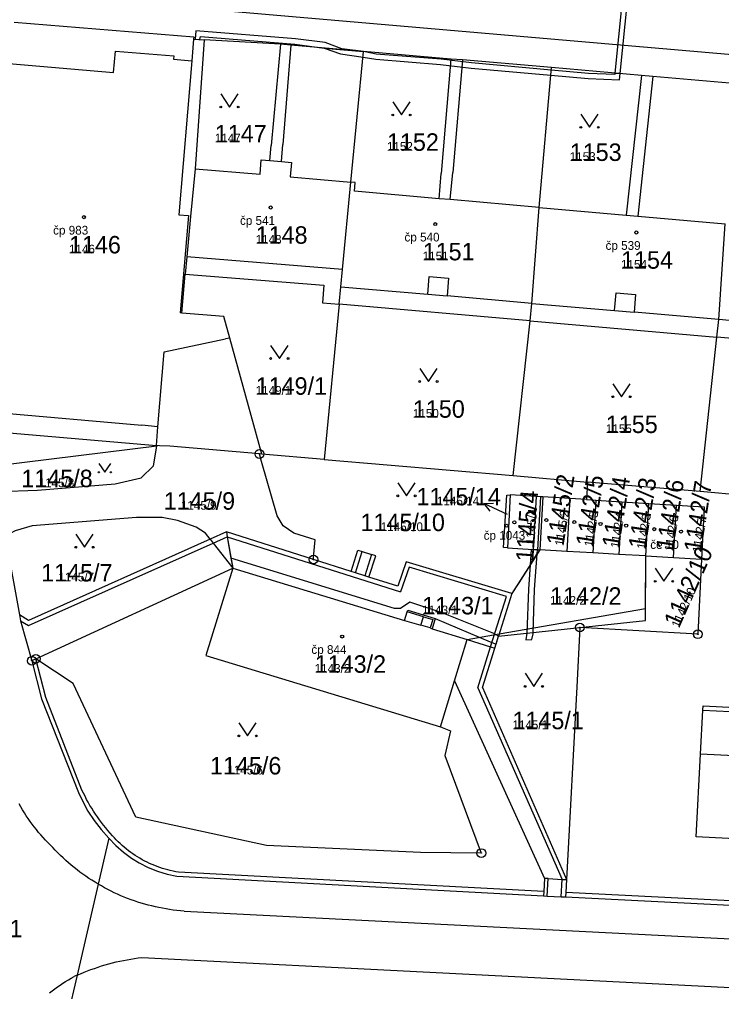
# Model space of a CAD drawing. Extents: x -763628 to -761565, y -976033 to -973833.
# Drawn here: x -762312.8 to -762232.3, y -975218.9 to -975107.6 of the extents above; entities that cross this region are included whole.
import ezdxf

# ---------------------------------------------------------------- set-up
doc = ezdxf.new("R2010")
doc.units = 0
for name, color, linetype in [('KN_cisla parcel 1000', 7, 'Continuous'), ('KN_cisla parcel 500', 7, 'Continuous'), ('KN_cisla parcel znacky', 7, 'Continuous'), ('KN_cisla popisna 500', 7, 'Continuous'), ('KN_hranice parcel', 7, 'Continuous'), ('KN_vecna bremena', 7, 'Continuous'), ('KN_vnitrni kresba parcel', 7, 'Continuous'), ('KN_znacky bodu BP', 7, 'Continuous'), ('KN_znacky budov', 7, 'Continuous'), ('KN_znacky kultur', 7, 'Continuous')]:
    doc.layers.add(name, color=color, linetype=linetype)

msp = doc.modelspace()

# ---------------------------------------------------------------- linework, layer by layer
at = {"layer": 'KN_cisla parcel znacky'}
for p, q in [((-762259.59, -975163.01), (-762258.47, -975162.98)), ((-762256.87, -975164.28), (-762259.59, -975163.01)), ((-762259.59, -975163.01), (-762258.89, -975163.89))]:
    msp.add_line(p, q, dxfattribs=at)
at = {"layer": 'KN_hranice parcel'}
for p, q in [((-762291.6, -975109.95), (-762292.65, -975124.69)), ((-762274.79, -975126.23), (-762273.34, -975111.26)), ((-762253.23, -975129.13), (-762251.83, -975113.12)), ((-762276.14, -975140.2), (-762277.84, -975157.98)), ((-762254.28, -975142.1), (-762276.14, -975140.2)), ((-762256.2, -975159.83), (-762254.28, -975142.1)), ((-762254.28, -975142.1), (-762232.88, -975143.96)), ((-762285.01, -975157.37), (-762288.68, -975144.08)), ((-762234.81, -975161.66), (-762232.88, -975143.96)), ((-762211.9, -975145.78), (-762232.88, -975143.96)), ((-762297.04, -975156.46), (-762315.51, -975158.72)), ((-762285.01, -975157.37), (-762285.28, -975157.35)), ((-762277.84, -975157.98), (-762285.01, -975157.37)), ((-762277.84, -975157.98), (-762256.2, -975159.83)), ((-762256.2, -975159.83), (-762247.7, -975160.56)), ((-762247.7, -975160.56), (-762247.81, -975162.58)), ((-762234.81, -975161.66), (-762247.7, -975160.56)), ((-762256.54, -975162.04), (-762256.88, -975168.08)), ((-762213.62, -975163.47), (-762234.81, -975161.66)), ((-762253.08, -975162.25), (-762253.42, -975168.33)), ((-762249.72, -975162.46), (-762250.05, -975168.51)), ((-762247.81, -975162.58), (-762249.72, -975162.46)), ((-762247.81, -975162.58), (-762246.75, -975162.65)), ((-762246.75, -975162.65), (-762247.08, -975168.68)), ((-762246.75, -975162.65), (-762243.78, -975162.83)), ((-762243.78, -975162.83), (-762244.11, -975168.84)), ((-762243.78, -975162.83), (-762240.67, -975163.02)), ((-762241, -975169.01), (-762240.67, -975163.02)), ((-762240.67, -975163.02), (-762237.5, -975163.22)), ((-762237.83, -975169.2), (-762237.5, -975163.22)), ((-762289.04, -975166.27), (-762290.9, -975167.1)), ((-762279.08, -975169.43), (-762289.04, -975166.27)), ((-762314.41, -975166.77), (-762312.74, -975175.77)), ((-762253.17, -975168.34), (-762256.35, -975173.33)), ((-762253.42, -975168.33), (-762253.17, -975168.34)), ((-762250.05, -975168.51), (-762253.17, -975168.34)), ((-762247.08, -975168.68), (-762250.05, -975168.51)), ((-762244.11, -975168.84), (-762247.08, -975168.68)), ((-762241, -975169.01), (-762244.11, -975168.84)), ((-762241, -975169.01), (-762237.83, -975169.2)), ((-762237.83, -975169.2), (-762234.66, -975169.38)), ((-762256.35, -975173.33), (-762257.89, -975178.21)), ((-762257.89, -975178.21), (-762248.58, -975177.21))]:
    msp.add_line(p, q, dxfattribs=at)
for points in [[(-762313.36, -975107.92), (-762292.79, -975109.61), (-762292.81, -975109.84), (-762291.6, -975109.95)], [(-762273.34, -975111.26), (-762281.67, -975110.54), (-762282.86, -975110.44), (-762291.6, -975109.95)], [(-762251.83, -975113.12), (-762262.01, -975112.24), (-762263.35, -975112.13), (-762273.34, -975111.26)], [(-762230.54, -975114.96), (-762240.22, -975114.12), (-762241.5, -975114.01), (-762251.83, -975113.12)], [(-762292.65, -975124.69), (-762285.2, -975125.33), (-762285.06, -975123.67), (-762284.1, -975123.75), (-762282.75, -975123.86), (-762281.6, -975123.96), (-762281.75, -975125.63), (-762274.79, -975126.23)], [(-762292.65, -975124.69), (-762293.16, -975130.17), (-762293.58, -975134.78), (-762293.76, -975136.76)], [(-762276.14, -975140.2), (-762275.95, -975138.21), (-762275.75, -975136.22), (-762274.79, -975126.23)], [(-762253.23, -975129.13), (-762263.41, -975128.23), (-762264.69, -975128.12), (-762274.39, -975127.27), (-762274.32, -975126.27), (-762274.79, -975126.23)], [(-762254.28, -975142.1), (-762254.07, -975140.11), (-762253.23, -975129.13)], [(-762253.23, -975129.13), (-762243.27, -975130), (-762241.95, -975130.12), (-762231.93, -975131)], [(-762232.88, -975143.96), (-762232.66, -975141.96), (-762231.93, -975131)], [(-762288.68, -975144.08), (-762289.36, -975141.6), (-762294.17, -975141.24), (-762293.76, -975136.76)], [(-762293.76, -975136.76), (-762277.9, -975138.04), (-762278.06, -975140.03), (-762276.14, -975140.2)], [(-762315.13, -975161.65), (-762310.69, -975161.48), (-762301.81, -975160.78), (-762298.83, -975160.07), (-762297.41, -975158.7), (-762297.04, -975156.46)], [(-762285.28, -975157.35), (-762295.55, -975156.47), (-762296.73, -975156.4), (-762297.06, -975156.37), (-762297.04, -975156.46)], [(-762279.08, -975169.43), (-762279.09, -975169.21), (-762278.88, -975167.18), (-762281.34, -975166.4), (-762282.55, -975165.59), (-762283.24, -975164.44), (-762285.02, -975158.21), (-762285.28, -975157.35)], [(-762256.88, -975168.08), (-762257.33, -975168.06), (-762256.92, -975162.05), (-762256.54, -975162.04)], [(-762253.08, -975162.25), (-762253.57, -975162.22), (-762256.54, -975162.04)], [(-762249.72, -975162.46), (-762252.83, -975162.27), (-762253.08, -975162.25)], [(-762237.5, -975163.22), (-762234.34, -975163.41), (-762234.66, -975169.38)], [(-762290.9, -975167.1), (-762291.44, -975166.4), (-762292.51, -975165.73), (-762294.67, -975164.95), (-762296.4, -975164.61), (-762299.35, -975164.63), (-762311.3, -975165.58), (-762313.26, -975166.16), (-762314.41, -975166.77)], [(-762289.04, -975166.27), (-762288.95, -975166.83), (-762288.33, -975170.44)], [(-762290.9, -975167.1), (-762311.71, -975176.42), (-762312.74, -975175.77)], [(-762256.88, -975168.08), (-762253.92, -975168.29), (-762253.42, -975168.33)], [(-762256.35, -975173.33), (-762268.48, -975169.68), (-762269.41, -975172.49), (-762272.73, -975171.44), (-762273.21, -975171.29), (-762274.28, -975170.95), (-762274.76, -975170.8), (-762279.08, -975169.43)], [(-762248.58, -975177.21), (-762241.05, -975176.43), (-762241, -975169.01)], [(-762234.66, -975169.38), (-762235.06, -975177.99), (-762248.58, -975177.21)], [(-762288.33, -975170.44), (-762291.41, -975180.43), (-762264.53, -975188.6)], [(-762288.33, -975170.44), (-762268.65, -975176.42), (-762268.34, -975175.41), (-762268.28, -975175.23), (-762265.14, -975176.18), (-762265.5, -975177.38), (-762261.49, -975178.6)], [(-762312.74, -975175.77), (-762312.62, -975176.44), (-762311.34, -975181.02)], [(-762248.58, -975177.21), (-762248.93, -975184), (-762250.1, -975206.07), (-762250.18, -975207.57), (-762250.2, -975208.06)], [(-762264.53, -975188.6), (-762262.92, -975183.31), (-762261.49, -975178.6)], [(-762261.49, -975178.6), (-762258.79, -975179.43), (-762258.32, -975179.57), (-762257.89, -975178.21)], [(-762264.53, -975188.6), (-762263.4, -975189.04), (-762264.05, -975191.88), (-762259.86, -975203.04), (-762266.82, -975202.96), (-762284.45, -975202.16), (-762299.41, -975198.93), (-762306.6, -975183.62), (-762310.88, -975180.81), (-762311.34, -975181.02)], [(-762311.34, -975181.02), (-762310.22, -975185.39), (-762306.01, -975196.11)], [(-762234.76, -975191.72), (-762234.5, -975186.69), (-762234.47, -975186.19), (-762219.72, -975186.93)], [(-762219.92, -975191.02), (-762223.83, -975190.82), (-762223.9, -975192.26), (-762234.76, -975191.72)], [(-762190.63, -975193.94), (-762191.1, -975203.43), (-762205.94, -975202.68), (-762220.45, -975201.95), (-762235.26, -975201.2), (-762234.76, -975191.72)], [(-762306.01, -975196.11), (-762305.44, -975197.3), (-762304.92, -975198.23), (-762304.2, -975199.32), (-762303.39, -975200.36), (-762302.51, -975201.34)], [(-762302.51, -975201.34), (-762303.73, -975206.6), (-762306.15, -975217.03), (-762308.35, -975226.49)], [(-762302.51, -975201.34), (-762301.72, -975202.17), (-762300.85, -975202.94), (-762299.93, -975203.62), (-762299.04, -975204.17), (-762298.02, -975204.69), (-762296.95, -975205.12), (-762295.85, -975205.46), (-762294.72, -975205.7)], [(-762294.72, -975205.7), (-762252.72, -975207.94), (-762252.32, -975207.96), (-762250.7, -975208.05), (-762250.2, -975208.06)], [(-762250.2, -975208.06), (-762178.53, -975211.68), (-762178.13, -975211.7), (-762176.93, -975211.76), (-762176.53, -975211.78)]]:
    msp.add_lwpolyline(points, dxfattribs=at)
at = {"layer": 'KN_vecna bremena'}
msp.add_lwpolyline([(-762243.72, -975105.45), (-762244.55, -975113.75), (-762243.96, -975113.8), (-762243.12, -975105.51)], dxfattribs=at)
for points in [[(-762292.55, -975108.91), (-762292.63, -975109.86), (-762292.08, -975109.91), (-762292.01, -975109.55), (-762281.21, -975110.43), (-762277.87, -975110.87), (-762273.34, -975111.26), (-762275.83, -975110.95), (-762277.73, -975110.25), (-762281.13, -975109.83)], [(-762273.34, -975111.26), (-762277.87, -975110.87), (-762275.99, -975111.53), (-762273.41, -975111.93), (-762271.96, -975112.16), (-762264.52, -975112.76), (-762261.04, -975113.16), (-762251.91, -975113.98), (-762247.64, -975114.37), (-762244.03, -975114.53), (-762243.96, -975113.8), (-762244.55, -975113.75), (-762244.57, -975113.91), (-762247.6, -975113.77), (-762251.85, -975113.39), (-762261, -975112.56), (-762264.46, -975112.16), (-762271.9, -975111.56)], [(-762289.04, -975166.27), (-762288.95, -975166.83), (-762288.53, -975169.28), (-762288.33, -975170.44), (-762268.65, -975176.42), (-762268.34, -975175.41), (-762268.28, -975175.23), (-762265.14, -975176.18), (-762265.5, -975177.38), (-762261.49, -975178.6), (-762257.81, -975177.96), (-762241.04, -975175.05), (-762241, -975169.01), (-762244.11, -975168.84), (-762247.08, -975168.68), (-762250.05, -975168.51), (-762253.17, -975168.34), (-762255.57, -975172.11), (-762256.35, -975173.33), (-762268.48, -975169.68), (-762269.41, -975172.49), (-762272.73, -975171.44), (-762273.21, -975171.29), (-762274.28, -975170.95), (-762274.76, -975170.8), (-762279.08, -975169.43)], [(-762253.45, -975168.79), (-762254.27, -975170.06), (-762254.46, -975172.81), (-762254.63, -975177.86), (-762254.78, -975178.64), (-762254.06, -975178.59), (-762253.93, -975177.93), (-762253.93, -975177.78), (-762253.76, -975172.85)], [(-762254.27, -975170.06), (-762253.45, -975168.79), (-762253.42, -975168.33), (-762254.14, -975168.27)], [(-762269.12, -975175.06), (-762269.81, -975175.04), (-762288.53, -975169.28), (-762288.33, -975170.44), (-762268.65, -975176.42), (-762268.34, -975175.41), (-762268.28, -975175.23), (-762265.14, -975176.18), (-762258.84, -975178.84), (-762258.17, -975179.11), (-762257.89, -975178.21), (-762258.44, -975177.92), (-762264.36, -975175.53), (-762268.06, -975174.32)]]:
    msp.add_lwpolyline(points, close=True, dxfattribs=at)
at = {"layer": 'KN_vnitrni kresba parcel'}
for p, q in [((-762313.23, -975104.5), (-762213.18, -975113.18)), ((-762292.81, -975109.84), (-762293.02, -975112.33)), ((-762282.86, -975110.44), (-762283.94, -975122.03)), ((-762281.67, -975110.54), (-762282.59, -975121.93)), ((-762301.97, -975113.66), (-762301.77, -975111.22)), ((-762301.77, -975111.22), (-762295.07, -975111.78)), ((-762295.07, -975111.78), (-762295.1, -975112.15)), ((-762263.35, -975112.13), (-762264.45, -975125.22)), ((-762313.98, -975112.63), (-762301.97, -975113.66)), ((-762295.1, -975112.15), (-762293.02, -975112.33)), ((-762293.02, -975112.33), (-762294.5, -975129.97)), ((-762262.01, -975112.24), (-762263.14, -975125.13)), ((-762241.5, -975114.01), (-762243.27, -975130)), ((-762240.22, -975114.12), (-762241.95, -975130.12)), ((-762284.1, -975123.75), (-762283.94, -975122.03)), ((-762282.75, -975123.86), (-762282.59, -975121.93)), ((-762264.69, -975128.12), (-762264.45, -975125.22)), ((-762263.41, -975128.23), (-762263.14, -975125.13)), ((-762294.5, -975129.97), (-762293.4, -975130.06)), ((-762293.4, -975130.06), (-762294.34, -975141.18)), ((-762275.75, -975136.22), (-762293.58, -975134.78)), ((-762266, -975139.07), (-762265.83, -975137.03)), ((-762265.83, -975137.03), (-762263.61, -975137.23)), ((-762263.61, -975137.23), (-762263.79, -975139.26)), ((-762275.95, -975138.21), (-762266, -975139.07)), ((-762266, -975139.07), (-762263.79, -975139.26)), ((-762254.07, -975140.11), (-762263.79, -975139.26)), ((-762244.61, -975140.93), (-762244.43, -975138.89)), ((-762244.43, -975138.89), (-762242.19, -975139.08)), ((-762242.19, -975139.08), (-762242.37, -975141.12)), ((-762254.07, -975140.11), (-762244.61, -975140.93)), ((-762244.61, -975140.93), (-762242.37, -975141.12)), ((-762294.17, -975141.24), (-762294.34, -975141.18)), ((-762232.66, -975141.96), (-762242.37, -975141.12)), ((-762223.18, -975142.78), (-762232.66, -975141.96)), ((-762296.19, -975145.64), (-762289.16, -975144.18)), ((-762288.68, -975144.08), (-762289.16, -975144.18)), ((-762296.89, -975154.23), (-762296.19, -975145.64)), ((-762316.65, -975152.49), (-762298.74, -975154.07)), ((-762296.89, -975154.23), (-762298.74, -975154.07)), ((-762297.06, -975156.37), (-762296.89, -975154.23)), ((-762316.03, -975154.76), (-762297.06, -975156.37)), ((-762253.57, -975162.22), (-762253.92, -975168.29)), ((-762252.83, -975162.27), (-762253.17, -975168.34)), ((-762311.72, -975177), (-762290.56, -975167.55)), ((-762290.9, -975167.1), (-762290.56, -975167.55)), ((-762290.56, -975167.55), (-762288.95, -975166.83)), ((-762290.56, -975167.55), (-762288.33, -975170.44)), ((-762288.95, -975166.83), (-762269.1, -975173.12)), ((-762274.76, -975170.8), (-762273.99, -975168.37)), ((-762274.28, -975170.95), (-762273.5, -975168.53)), ((-762273.99, -975168.37), (-762273.5, -975168.53)), ((-762273.5, -975168.53), (-762272.44, -975168.86)), ((-762272.44, -975168.86), (-762273.21, -975171.29)), ((-762271.96, -975169.01), (-762272.44, -975168.86)), ((-762272.73, -975171.44), (-762271.96, -975169.01)), ((-762310.88, -975180.81), (-762288.33, -975170.44)), ((-762268.14, -975170.3), (-762269.1, -975173.12)), ((-762256.97, -975173.67), (-762268.14, -975170.3)), ((-762258.79, -975179.43), (-762256.97, -975173.67)), ((-762266.48, -975175.98), (-762268.34, -975175.41)), ((-762312.62, -975176.44), (-762311.72, -975177)), ((-762268.65, -975176.42), (-762266.78, -975176.94)), ((-762266.78, -975176.94), (-762266.48, -975175.98)), ((-762266.48, -975175.98), (-762265.43, -975176.3)), ((-762265.43, -975176.3), (-762265.72, -975177.26)), ((-762265.72, -975177.26), (-762266.78, -975176.94)), ((-762265.72, -975177.26), (-762265.5, -975177.38)), ((-762260.27, -975184.11), (-762258.79, -975179.43)), ((-762259.73, -975184.07), (-762258.32, -975179.57)), ((-762309.75, -975185.22), (-762310.88, -975180.81)), ((-762262.92, -975183.31), (-762252.61, -975205.94)), ((-762260.27, -975184.11), (-762250.6, -975206.05)), ((-762259.73, -975184.07), (-762250.1, -975206.07)), ((-762305.6, -975195.83), (-762309.75, -975185.22)), ((-762234.5, -975186.69), (-762219.74, -975187.43)), ((-762252.69, -975207.44), (-762294.55, -975205.23)), ((-762252.61, -975205.94), (-762252.69, -975207.44)), ((-762252.21, -975205.96), (-762252.61, -975205.94)), ((-762252.32, -975207.96), (-762252.21, -975205.96)), ((-762252.21, -975205.96), (-762250.6, -975206.05)), ((-762250.7, -975208.05), (-762250.6, -975206.05)), ((-762250.6, -975206.05), (-762250.1, -975206.07)), ((-762252.69, -975207.44), (-762252.72, -975207.94)), ((-762178.5, -975211.18), (-762250.18, -975207.57)), ((-762293.91, -975209.68), (-762200.41, -975214.45)), ((-762298.75, -975214.99), (-762200.57, -975220.01))]:
    msp.add_line(p, q, dxfattribs=at)
for points in [[(-762302.1, -975201.05), (-762302.36, -975200.76), (-762302.62, -975200.46), (-762302.88, -975200.16), (-762303.13, -975199.85), (-762303.37, -975199.54), (-762303.6, -975199.22), (-762303.83, -975198.9), (-762304.06, -975198.58), (-762304.27, -975198.25), (-762304.48, -975197.91), (-762304.69, -975197.58), (-762304.88, -975197.23), (-762305.07, -975196.89), (-762305.25, -975196.54), (-762305.43, -975196.19), (-762305.6, -975195.83)], [(-762308.94, -975202.41), (-762309.22, -975202.13), (-762309.5, -975201.85), (-762309.78, -975201.56), (-762310.04, -975201.27), (-762310.3, -975200.97), (-762310.56, -975200.67), (-762310.81, -975200.36), (-762311.06, -975200.05), (-762311.3, -975199.74), (-762311.53, -975199.42), (-762311.76, -975199.09), (-762311.98, -975198.76), (-762312.19, -975198.43), (-762312.4, -975198.09), (-762312.6, -975197.75), (-762312.8, -975197.4)], [(-762294.55, -975205.23), (-762294.86, -975205.18), (-762295.17, -975205.11), (-762295.48, -975205.05), (-762295.78, -975204.97), (-762296.08, -975204.89), (-762296.38, -975204.79), (-762296.68, -975204.7), (-762296.98, -975204.59), (-762297.27, -975204.48), (-762297.56, -975204.35), (-762297.85, -975204.23), (-762298.13, -975204.09), (-762298.41, -975203.95), (-762298.69, -975203.8), (-762298.96, -975203.64), (-762299.23, -975203.48), (-762299.5, -975203.31), (-762299.76, -975203.14), (-762300.02, -975202.96), (-762300.27, -975202.77), (-762300.52, -975202.57), (-762300.76, -975202.37), (-762300.99, -975202.17), (-762301.23, -975201.95), (-762301.45, -975201.74), (-762301.67, -975201.51), (-762301.89, -975201.28), (-762302.1, -975201.05)], [(-762303.73, -975206.6), (-762304.09, -975206.39), (-762304.45, -975206.16), (-762304.8, -975205.94), (-762305.15, -975205.7), (-762305.49, -975205.46), (-762305.83, -975205.21), (-762306.16, -975204.96), (-762306.49, -975204.7), (-762306.82, -975204.43), (-762307.14, -975204.16), (-762307.45, -975203.88), (-762307.76, -975203.6), (-762308.06, -975203.31), (-762308.36, -975203.02), (-762308.65, -975202.72), (-762308.94, -975202.41)], [(-762293.91, -975209.68), (-762294.32, -975209.65), (-762294.74, -975209.61), (-762295.15, -975209.56), (-762295.56, -975209.5), (-762295.97, -975209.43), (-762296.38, -975209.36), (-762296.79, -975209.28), (-762297.19, -975209.2), (-762297.6, -975209.1), (-762298, -975209), (-762298.4, -975208.89), (-762298.8, -975208.77), (-762299.2, -975208.65), (-762299.59, -975208.52), (-762299.98, -975208.38), (-762300.37, -975208.23), (-762300.76, -975208.08), (-762301.14, -975207.92), (-762301.52, -975207.75), (-762301.9, -975207.58), (-762302.27, -975207.39), (-762302.64, -975207.21), (-762303.01, -975207.01), (-762303.37, -975206.81), (-762303.73, -975206.6)], [(-762306.15, -975217.03), (-762305.76, -975216.86), (-762305.36, -975216.69), (-762304.97, -975216.54), (-762304.57, -975216.38), (-762304.16, -975216.24), (-762303.76, -975216.1), (-762303.35, -975215.97), (-762302.94, -975215.85), (-762302.53, -975215.73), (-762302.11, -975215.62), (-762301.7, -975215.51), (-762301.28, -975215.42), (-762300.86, -975215.33), (-762300.44, -975215.25), (-762300.02, -975215.17), (-762299.6, -975215.1), (-762299.18, -975215.04), (-762298.75, -975214.99)], [(-762309.3, -975219.04), (-762309.01, -975218.81), (-762308.71, -975218.59), (-762308.41, -975218.37), (-762308.1, -975218.15), (-762307.79, -975217.95), (-762307.47, -975217.75), (-762307.15, -975217.56), (-762306.83, -975217.37), (-762306.5, -975217.19)], [(-762306.15, -975217.03), (-762306.33, -975217.11), (-762306.5, -975217.19)]]:
    msp.add_lwpolyline(points, dxfattribs=at)
at = {"layer": 'KN_znacky bodu BP'}
for centre, radius in [((-762285.28, -975157.35), 0.5), ((-762285.28, -975157.35), 0.0303), ((-762279.08, -975169.43), 0.5), ((-762279.08, -975169.43), 0.0303), ((-762248.58, -975177.21), 0.5), ((-762248.58, -975177.21), 0.0303), ((-762235.06, -975177.99), 0.5), ((-762235.06, -975177.99), 0.0303), ((-762311.34, -975181.02), 0.5), ((-762310.88, -975180.81), 0.5), ((-762311.34, -975181.02), 0.0303), ((-762310.88, -975180.81), 0.0303), ((-762259.86, -975203.04), 0.5), ((-762259.86, -975203.04), 0.0303)]:
    msp.add_circle(centre, radius, dxfattribs=at)
at = {"layer": 'KN_znacky budov'}
for centre in [(-762283.98, -975129.13), (-762305.38, -975130.24), (-762265.14, -975131.03), (-762242.11, -975131.99), (-762256.95, -975165.57), (-762256.07, -975165.18), (-762252.41, -975164.92), (-762249.21, -975165.15), (-762246.21, -975165.36), (-762243.27, -975165.55), (-762240.06, -975165.96), (-762236.99, -975166.23), (-762275.8, -975178.25)]:
    msp.add_circle(centre, 0.175, dxfattribs=at)
at = {"layer": 'KN_znacky kultur'}
for points in [[(-762289.7, -975116.13), (-762288.7, -975117.63), (-762287.7, -975116.13)], [(-762270, -975117.04), (-762269, -975118.54), (-762268, -975117.04)], [(-762248.46, -975118.45), (-762247.46, -975119.95), (-762246.46, -975118.45)], [(-762283.99, -975144.92), (-762282.99, -975146.42), (-762281.99, -975144.92)], [(-762266.92, -975147.55), (-762265.92, -975149.05), (-762264.92, -975147.55)], [(-762244.8, -975149.3), (-762243.8, -975150.8), (-762242.8, -975149.3)], [(-762303.66, -975158.43), (-762302.98, -975159.45), (-762302.3, -975158.43)], [(-762269.43, -975160.64), (-762268.43, -975162.14), (-762267.43, -975160.64)], [(-762306.31, -975166.53), (-762305.31, -975168.03), (-762304.31, -975166.53)], [(-762239.94, -975170.43), (-762238.94, -975171.93), (-762237.94, -975170.43)], [(-762254.85, -975182.46), (-762253.85, -975183.96), (-762252.85, -975182.46)], [(-762287.63, -975188.13), (-762286.63, -975189.63), (-762285.63, -975188.13)]]:
    msp.add_lwpolyline(points, dxfattribs=at)
for centre, radius in [((-762289.7, -975117.63), 0.1), ((-762287.7, -975117.63), 0.1), ((-762270, -975118.54), 0.1), ((-762268, -975118.54), 0.1), ((-762248.46, -975119.95), 0.1), ((-762246.46, -975119.95), 0.1), ((-762283.99, -975146.42), 0.1), ((-762281.99, -975146.42), 0.1), ((-762266.92, -975149.05), 0.1), ((-762264.92, -975149.05), 0.1), ((-762244.8, -975150.8), 0.1), ((-762242.8, -975150.8), 0.1), ((-762303.66, -975159.45), 0.068), ((-762302.3, -975159.45), 0.068), ((-762269.43, -975162.14), 0.1), ((-762267.43, -975162.14), 0.1), ((-762306.31, -975168.03), 0.1), ((-762304.31, -975168.03), 0.1), ((-762239.94, -975171.93), 0.1), ((-762237.94, -975171.93), 0.1), ((-762254.85, -975183.96), 0.1), ((-762252.85, -975183.96), 0.1), ((-762287.63, -975189.63), 0.1), ((-762285.63, -975189.63), 0.1)]:
    msp.add_circle(centre, radius, dxfattribs=at)

# ---------------------------------------------------------------- texts
at = {"layer": 'KN_cisla parcel 1000'}
for s, p in [('1147', (-762290.39, -975121.68)), ('1152', (-762270.67, -975122.64)), ('1153', (-762249.74, -975123.8)), ('1148', (-762285.71, -975133.28)), ('1146', (-762307.09, -975134.39)), ('1151', (-762266.58, -975135.18)), ('1154', (-762243.86, -975136.14)), ('1149/1', (-762285.71, -975150.57)), ('1150', (-762267.7, -975153.2)), ('1155', (-762245.6, -975154.95)), ('1145/8', (-762312.55, -975161.15)), ('1145/9', (-762296.24, -975163.73)), ('1145/14', (-762267.29, -975163.23)), ('1145/10', (-762273.7, -975166.18)), ('1145/7', (-762310.28, -975171.94)), ('1142/2', (-762251.99, -975174.61)), ('1143/1', (-762266.64, -975175.71)), ('1143/2', (-762278.95, -975182.4)), ('1145/1', (-762256.3, -975188.86)), ('1145/6', (-762290.94, -975194.04)), ('1969/1', (-762320.61, -975212.69))]:
    msp.add_text(s, height=2, dxfattribs=at).set_placement(p)
for s, rotation, p in [('1145/2', 81, (-762250.45, -975167.93)), ('1142/5', 81, (-762247.09, -975168.02)), ('1142/4', 81, (-762244.09, -975168.17)), ('1142/3', 81, (-762241.07, -975168.31)), ('1142/6', 81, (-762237.91, -975168.52)), ('1142/7', 81, (-762234.71, -975168.69)), ('1145/4', 86, (-762253.92, -975169.74)), ('1142/10', 66, (-762237.21, -975177.34))]:
    msp.add_text(s, height=2, rotation=rotation, dxfattribs=at).set_placement(p)
at = {"layer": 'KN_cisla parcel 500'}
for s, p in [('1147', (-762290.39, -975121.68)), ('1152', (-762270.67, -975122.64)), ('1153', (-762249.74, -975123.8)), ('1148', (-762285.71, -975133.28)), ('1146', (-762307.09, -975134.39)), ('1151', (-762266.58, -975135.18)), ('1154', (-762243.86, -975136.14)), ('1149/1', (-762285.71, -975150.57)), ('1150', (-762267.7, -975153.2)), ('1155', (-762245.6, -975154.95)), ('1145/8', (-762310.57, -975161.15)), ('1145/14', (-762264.95, -975163.23)), ('1145/9', (-762294.27, -975163.73)), ('1145/10', (-762271.38, -975166.18)), ('1145/7', (-762308.3, -975171.94)), ('1142/2', (-762251.99, -975174.61)), ('1143/1', (-762266.64, -975175.71)), ('1143/2', (-762278.95, -975182.4)), ('1145/1', (-762256.3, -975188.86)), ('1145/6', (-762288.96, -975194.04))]:
    msp.add_text(s, height=1, dxfattribs=at).set_placement(p)
for s, rotation, p in [('1145/4', 86, (-762253.78, -975167.74)), ('1145/2', 81, (-762250.45, -975167.93)), ('1142/5', 81, (-762247.09, -975168.02)), ('1142/4', 81, (-762244.09, -975168.17)), ('1142/3', 81, (-762241.07, -975168.31)), ('1142/6', 81, (-762237.91, -975168.52)), ('1142/7', 81, (-762234.71, -975168.69)), ('1142/10', 66, (-762237.21, -975177.34))]:
    msp.add_text(s, height=1, rotation=rotation, dxfattribs=at).set_placement(p)
at = {"layer": 'KN_cisla popisna 500'}
for s, p in [('čp 541', (-762287.5, -975131.12)), ('čp 983', (-762308.9, -975132.23)), ('čp 540', (-762268.66, -975133.02)), ('čp 539', (-762245.63, -975133.98)), ('čp 1043', (-762259.59, -975167.17)), ('če 10', (-762240.51, -975168.22)), ('čp 844', (-762279.32, -975180.24))]:
    msp.add_text(s, height=1, dxfattribs=at).set_placement(p)

doc.saveas('drawing.dxf')
